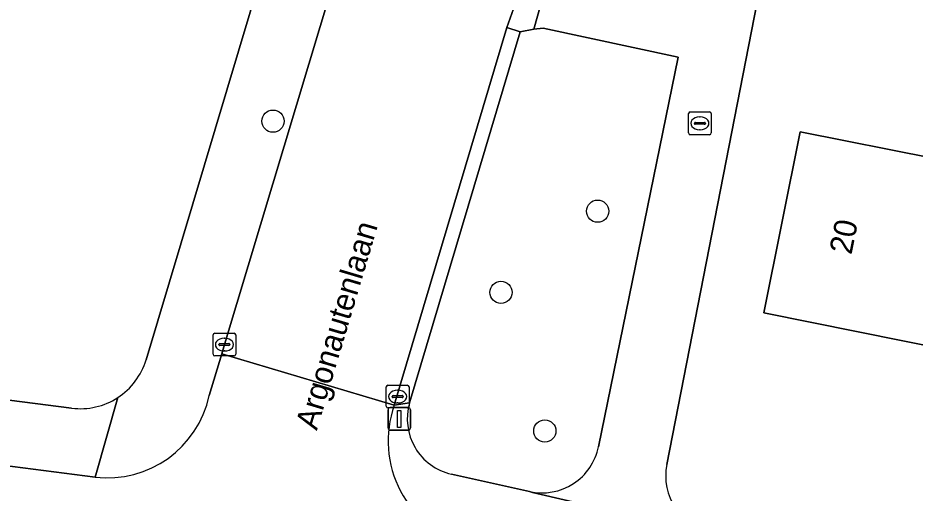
# Model space of a CAD drawing. Extents: x 162184 to 163154, y 385507 to 386516.
# Drawn here: x 162505.32 to 162544.83, y 385954.92 to 385975.84 of the extents above; entities that cross this region are included whole.
import ezdxf

# ---------------------------------------------------------------- set-up
doc = ezdxf.new("R2010")
doc.units = 0
for name, color, linetype in [('IMGEO_Boom', 7, 'Continuous'), ('IMGEO_Brandkraan', 7, 'Continuous'), ('IMGEO_Erf', 7, 'Continuous'), ('IMGEO_Groenvoorziening', 7, 'Continuous'), ('IMGEO_Kolk', 7, 'Continuous'), ('IMGEO_Lichtmast', 7, 'Continuous'), ('IMGEO_Openbare_ruimte_label', 7, 'Continuous'), ('IMGEO_Pand', 7, 'Continuous'), ('IMGEO_Pand_nummerreeks', 7, 'Continuous'), ('IMGEO_Rijbaan_lokaal_gesloten', 7, 'Continuous'), ('IMGEO_Rijbaan_lokaal_open', 7, 'Continuous'), ('IMGEO_Voetpad_open', 7, 'Continuous')]:
    doc.layers.add(name, color=color, linetype=linetype)

msp = doc.modelspace()

# ---------------------------------------------------------------- linework, layer by layer
at = {"layer": 'IMGEO_Boom'}
for centre in [(162516.552, 385971.295), (162530.85, 385967.33), (162526.595, 385963.756), (162528.524, 385957.654)]:
    msp.add_circle(centre, 0.489, dxfattribs=at)
at = {"layer": 'IMGEO_Brandkraan'}
for p, q in [((162534.852, 385970.773), (162534.852, 385971.625)), ((162534.927, 385971.699), (162535.779, 385971.699)), ((162535.34, 385971.479), (162535.365, 385971.479)), ((162535.853, 385971.625), (162535.853, 385970.773)), ((162535.111, 385971.193), (162535.111, 385971.205)), ((162535.549, 385971.156), (162535.151, 385971.156)), ((162535.154, 385971.242), (162535.552, 385971.242)), ((162535.595, 385971.205), (162535.595, 385971.193)), ((162535.779, 385970.699), (162534.927, 385970.699)), ((162535.363, 385970.919), (162535.338, 385970.919))]:
    msp.add_line(p, q, dxfattribs=at)
for points in [[(162534.852, 385970.773), (162534.852, 385971.625)], [(162534.927, 385971.699), (162535.779, 385971.699)], [(162535.853, 385971.625), (162535.853, 385970.773)], [(162535.779, 385970.699), (162534.927, 385970.699)]]:
    msp.add_lwpolyline(points, dxfattribs=at)
for centre, radius, start, end in [((162534.929, 385971.623), 0.0765, 91.552, 178.448), ((162534.929, 385971.623), 0.0765, 91.552, 178.448), ((162535.777, 385971.623), 0.0765, 1.552, 88.448), ((162535.777, 385971.623), 0.0765, 1.552, 88.448), ((162535.151, 385971.202), 0.0403, 85.8775, 175.7526), ((162535.148, 385971.192), 0.0366, 178.938, 274.7102), ((162535.552, 385971.199), 0.043, 264.8664, 352.4533), ((162535.556, 385971.204), 0.0386, 1.7309, 96.639), ((162534.929, 385970.775), 0.0765, 181.552, 268.448), ((162534.929, 385970.775), 0.0765, 181.552, 268.448), ((162535.777, 385970.775), 0.0765, 271.552, 358.448), ((162535.777, 385970.775), 0.0765, 271.552, 358.448)]:
    msp.add_arc(centre, radius, start, end, dxfattribs=at)
for centre, major_axis, ratio, start_param, end_param in [((162535.339, 385971.199), (-0.387, 0.002), 0.722429, 4.712389, 7.853982), ((162535.364, 385971.199), (-0.39, 0.002), 0.717154, 1.570796, 4.712389)]:
    msp.add_ellipse(centre, major_axis=major_axis, ratio=ratio, start_param=start_param, end_param=end_param, dxfattribs=at)
at = {"layer": 'IMGEO_Erf'}
for points in [[(162422.348, 386033.225), (162418.561, 386004.261), (162419.289, 386004.166), (162419.601, 386006.591), (162422.654, 386006.198), (162422.341, 386003.767), (162423.388, 386003.63), (162422.904, 386000), (162419.894, 385976.404), (162419.079, 385970.015), (162500, 385959.644), (162507.69, 385958.658)], [(162545.809, 386015.54), (162542.711, 386000), (162538.512, 385978.937), (162537.876, 385976.531), (162533.9, 385956.179)], [(162510.965, 385960.784), (162522.698, 386000)]]:
    msp.add_lwpolyline(points, dxfattribs=at)
msp.add_lwpolyline([(162550.855, 385964.67), (162549.284, 385964.986), (162548.44, 385960.786), (162538.168, 385962.851), (162539.773, 385970.831), (162545.684, 385969.643), (162546.66, 385974.496), (162556.896, 385972.438), (162561.004, 385971.612), (162559.845, 385965.846), (162555.736, 385966.672), (162555.895, 385967.46), (162551.59, 385968.326)], close=True, dxfattribs=at)
for centre, radius, start, end in [((162508.072, 385961.652), 3.02, 303.0161, 343.2882), ((162508.074, 385961.655), 3.022, 262.7017, 302.9654), ((162536.46, 385955.669), 2.611, 168.7392, 256.864)]:
    msp.add_arc(centre, radius, start, end, dxfattribs=at)
at = {"layer": 'IMGEO_Groenvoorziening'}
for points in [[(162530.892, 385956.961), (162534.4, 385974.112), (162528.456, 385975.388), (162528.043, 385975.34), (162527.434, 385975.23), (162522.572, 385958.886)], [(162524.41, 385955.756), (162527.847, 385954.989)]]:
    msp.add_lwpolyline(points, dxfattribs=at)
for centre, radius, start, end in [((162524.952, 385958.179), 2.483, 163.4603, 257.3843), ((162528.401, 385957.47), 2.542, 257.4014, 348.4543)]:
    msp.add_arc(centre, radius, start, end, dxfattribs=at)
at = {"layer": 'IMGEO_Kolk'}
for p, q in [((162513.917, 385961.032), (162513.917, 385961.884)), ((162513.992, 385961.958), (162514.844, 385961.958)), ((162514.918, 385961.884), (162514.918, 385961.032)), ((162514.219, 385961.501), (162514.617, 385961.501)), ((162514.405, 385961.738), (162514.43, 385961.738)), ((162514.176, 385961.452), (162514.176, 385961.464)), ((162514.614, 385961.415), (162514.216, 385961.415)), ((162514.428, 385961.178), (162514.403, 385961.178)), ((162514.66, 385961.464), (162514.66, 385961.452)), ((162514.844, 385960.958), (162513.992, 385960.958)), ((162521.544, 385958.741), (162521.544, 385959.593)), ((162521.619, 385959.667), (162522.471, 385959.667)), ((162522.545, 385959.593), (162522.545, 385958.741)), ((162521.803, 385959.161), (162521.803, 385959.173)), ((162522.241, 385959.124), (162521.843, 385959.124)), ((162521.846, 385959.21), (162522.244, 385959.21)), ((162522.032, 385959.447), (162522.057, 385959.447)), ((162522.287, 385959.173), (162522.287, 385959.161)), ((162522.055, 385958.887), (162522.03, 385958.887)), ((162522.471, 385958.667), (162521.619, 385958.667))]:
    msp.add_line(p, q, dxfattribs=at)
for points in [[(162513.917, 385961.032), (162513.917, 385961.884)], [(162513.992, 385961.958), (162514.844, 385961.958)], [(162514.918, 385961.884), (162514.918, 385961.032)], [(162514.844, 385960.958), (162513.992, 385960.958)], [(162521.544, 385958.741), (162521.544, 385959.593)], [(162521.619, 385959.667), (162522.471, 385959.667)], [(162522.545, 385959.593), (162522.545, 385958.741)], [(162522.471, 385958.667), (162521.619, 385958.667)]]:
    msp.add_lwpolyline(points, dxfattribs=at)
for centre, radius, start, end in [((162513.994, 385961.882), 0.0765, 91.552, 178.448), ((162513.994, 385961.882), 0.0765, 91.552, 178.448), ((162514.842, 385961.882), 0.0765, 1.552, 88.448), ((162514.842, 385961.882), 0.0765, 1.552, 88.448), ((162514.216, 385961.461), 0.0403, 85.8775, 175.7526), ((162514.621, 385961.463), 0.0386, 1.7309, 96.639), ((162514.213, 385961.451), 0.0366, 178.938, 274.7102), ((162514.617, 385961.458), 0.043, 264.8664, 352.4533), ((162513.994, 385961.034), 0.0765, 181.552, 268.448), ((162513.994, 385961.034), 0.0765, 181.552, 268.448), ((162514.842, 385961.034), 0.0765, 271.552, 358.448), ((162514.842, 385961.034), 0.0765, 271.552, 358.448), ((162521.621, 385959.591), 0.0765, 91.552, 178.448), ((162521.621, 385959.591), 0.0765, 91.552, 178.448), ((162522.469, 385959.591), 0.0765, 1.552, 88.448), ((162522.469, 385959.591), 0.0765, 1.552, 88.448), ((162521.843, 385959.17), 0.0403, 85.8775, 175.7526), ((162521.84, 385959.16), 0.0366, 178.938, 274.7102), ((162522.244, 385959.167), 0.043, 264.8664, 352.4533), ((162522.248, 385959.172), 0.0386, 1.7309, 96.639), ((162521.621, 385958.743), 0.0765, 181.552, 268.448), ((162521.621, 385958.743), 0.0765, 181.552, 268.448), ((162522.469, 385958.743), 0.0765, 271.552, 358.448), ((162522.469, 385958.743), 0.0765, 271.552, 358.448)]:
    msp.add_arc(centre, radius, start, end, dxfattribs=at)
for centre, major_axis, ratio, start_param, end_param in [((162514.404, 385961.458), (-0.387, 0.002), 0.722429, 4.712389, 7.853982), ((162514.429, 385961.458), (-0.39, 0.002), 0.717154, 1.570796, 4.712389), ((162522.031, 385959.167), (-0.387, 0.002), 0.722429, 4.712389, 7.853982), ((162522.056, 385959.167), (-0.39, 0.002), 0.717154, 1.570796, 4.712389)]:
    msp.add_ellipse(centre, major_axis=major_axis, ratio=ratio, start_param=start_param, end_param=end_param, dxfattribs=at)
at = {"layer": 'IMGEO_Lichtmast'}
for p, q in [((162521.62, 385957.786), (162521.62, 385958.586)), ((162521.62, 385958.586), (162521.62, 385957.786)), ((162521.72, 385958.686), (162522.51, 385958.686)), ((162522.51, 385958.686), (162521.72, 385958.686)), ((162522.61, 385958.586), (162522.61, 385957.786)), ((162522.61, 385957.786), (162522.61, 385958.586)), ((162522.51, 385957.686), (162521.72, 385957.686)), ((162521.72, 385957.686), (162522.51, 385957.686))]:
    msp.add_line(p, q, dxfattribs=at)
msp.add_lwpolyline([(162522.04, 385958.561), (162522.19, 385958.561), (162522.19, 385957.811), (162522.04, 385957.811), (162522.04, 385958.561)], dxfattribs=at)
for centre, start, end in [((162521.72, 385958.586), 90, 180), ((162521.72, 385958.586), 90, 180), ((162522.51, 385958.586), 0, 90), ((162522.51, 385958.586), 360, 90), ((162521.72, 385957.786), 180, 270), ((162521.72, 385957.786), 180, 270), ((162522.51, 385957.786), 270, 0), ((162522.51, 385957.786), 270, 0)]:
    msp.add_arc(centre, 0.1, start, end, dxfattribs=at)
at = {"layer": 'IMGEO_Pand'}
msp.add_lwpolyline([(162549.284, 385964.986), (162550.855, 385964.67), (162551.59, 385968.326), (162555.895, 385967.46), (162556.896, 385972.438), (162546.66, 385974.496), (162545.684, 385969.643), (162539.773, 385970.831), (162538.168, 385962.851), (162548.44, 385960.786)], close=True, dxfattribs=at)
at = {"layer": 'IMGEO_Rijbaan_lokaal_gesloten'}
msp.add_lwpolyline([(162556.224, 386101.164), (162536.876, 386036.467), (162531.5, 386018.514), (162531.472, 386018.406), (162525.969, 386000), (162525.545, 385998.581), (162524.49, 385995.049), (162520.208, 385980.718), (162519.777, 385979.293), (162519.173, 385977.285), (162514.415, 385961.458), (162514.302, 385961.048), (162521.898, 385958.783), (162526.858, 385975.418), (162527.361, 385976.875), (162527.77, 385978.466), (162532.151, 385993.098), (162533.268, 385996.826), (162534.218, 386000), (162539.573, 386018.286), (162544.709, 386035.795), (162552.598, 386062.092)], dxfattribs=at)
at = {"layer": 'IMGEO_Rijbaan_lokaal_open'}
for points in [[(162521.898, 385958.783), (162514.302, 385961.048), (162513.749, 385959.214)], [(162508.728, 385955.623), (162504.634, 385956.15), (162503.658, 385949.12)]]:
    msp.add_lwpolyline(points, dxfattribs=at)
for centre, radius, start, end in [((162509.269, 385960.173), 4.582, 263.2227, 347.9217), ((162526.337, 385957.208), 4.71, 160.469, 255.2628)]:
    msp.add_arc(centre, radius, start, end, dxfattribs=at)
at = {"layer": 'IMGEO_Voetpad_open'}
for points in [[(162530.63, 386023.303), (162528.389, 386019.021), (162522.698, 386000), (162510.965, 385960.784)], [(162542.986, 386016.54), (162539.616, 386000), (162538.534, 385994.688), (162534.648, 385995.479), (162534.23, 385996.154), (162533.303, 385993.021), (162533.778, 385993.128), (162537.889, 385992.192), (162534.751, 385976.26), (162529.024, 385977.522), (162528.726, 385977.814), (162528.043, 385975.34), (162528.456, 385975.388), (162534.4, 385974.112), (162530.892, 385956.961)], [(162533.9, 385956.179), (162537.876, 385976.531), (162538.512, 385978.937), (162542.711, 386000)], [(162513.749, 385959.214), (162514.302, 385961.048), (162514.415, 385961.458), (162519.173, 385977.285), (162518.695, 385977.429), (162519.73, 385980.862), (162520.208, 385980.718), (162524.49, 385995.049)], [(162404.689, 385968.943), (162431.689, 385965.478), (162431.747, 385965.978), (162438.188, 385965.158), (162438.129, 385964.652), (162454.319, 385962.574), (162454.376, 385963.056), (162458.142, 385962.564), (162458.086, 385962.091), (162470.976, 385960.437), (162471.029, 385960.881), (162474.908, 385960.374), (162474.856, 385959.939), (162475.648, 385959.837), (162475.699, 385960.271), (162478.945, 385959.861), (162478.889, 385959.402), (162486.094, 385958.582), (162500, 385956.76), (162503.537, 385956.297), (162504.634, 385956.15), (162508.728, 385955.623), (162509.718, 385959.12)], [(162507.69, 385958.658), (162500, 385959.644)], [(162509.718, 385959.12), (162508.728, 385955.623)], [(162522.572, 385958.886), (162521.898, 385958.783)], [(162535.867, 385953.127), (162535.719, 385953.15), (162527.976, 385954.947), (162527.847, 385954.989), (162524.41, 385955.756)], [(162527.847, 385954.989), (162527.976, 385954.947), (162535.719, 385953.15), (162535.867, 385953.127)]]:
    msp.add_lwpolyline(points, dxfattribs=at)
for points in [[(162527.77, 385978.466), (162527.361, 385976.875), (162526.858, 385975.418), (162527.434, 385975.23), (162528.043, 385975.34), (162528.726, 385977.814), (162528.315, 385978.313)], [(162527.434, 385975.23), (162526.858, 385975.418), (162521.898, 385958.783), (162522.572, 385958.886)]]:
    msp.add_lwpolyline(points, close=True, dxfattribs=at)
for centre, radius, start, end in [((162508.072, 385961.652), 3.02, 303.0161, 343.2882), ((162508.074, 385961.655), 3.022, 262.7017, 302.9654), ((162509.269, 385960.173), 4.582, 263.2227, 347.9217), ((162526.337, 385957.208), 4.71, 160.469, 255.2628), ((162524.952, 385958.179), 2.483, 163.4603, 257.3843), ((162528.401, 385957.47), 2.542, 257.4014, 348.4543), ((162536.46, 385955.669), 2.611, 168.7392, 256.864)]:
    msp.add_arc(centre, radius, start, end, dxfattribs=at)

# ---------------------------------------------------------------- texts
at = {"layer": 'IMGEO_Openbare_ruimte_label'}
msp.add_text('Argonautenlaan', height=1, rotation=73.4325, dxfattribs=at).set_placement((162518.486, 385957.648))
at = {"layer": 'IMGEO_Pand_nummerreeks'}
msp.add_text('20', height=1, rotation=78.6279, dxfattribs=at).set_placement((162542.025, 385965.387))

doc.saveas('drawing.dxf')
